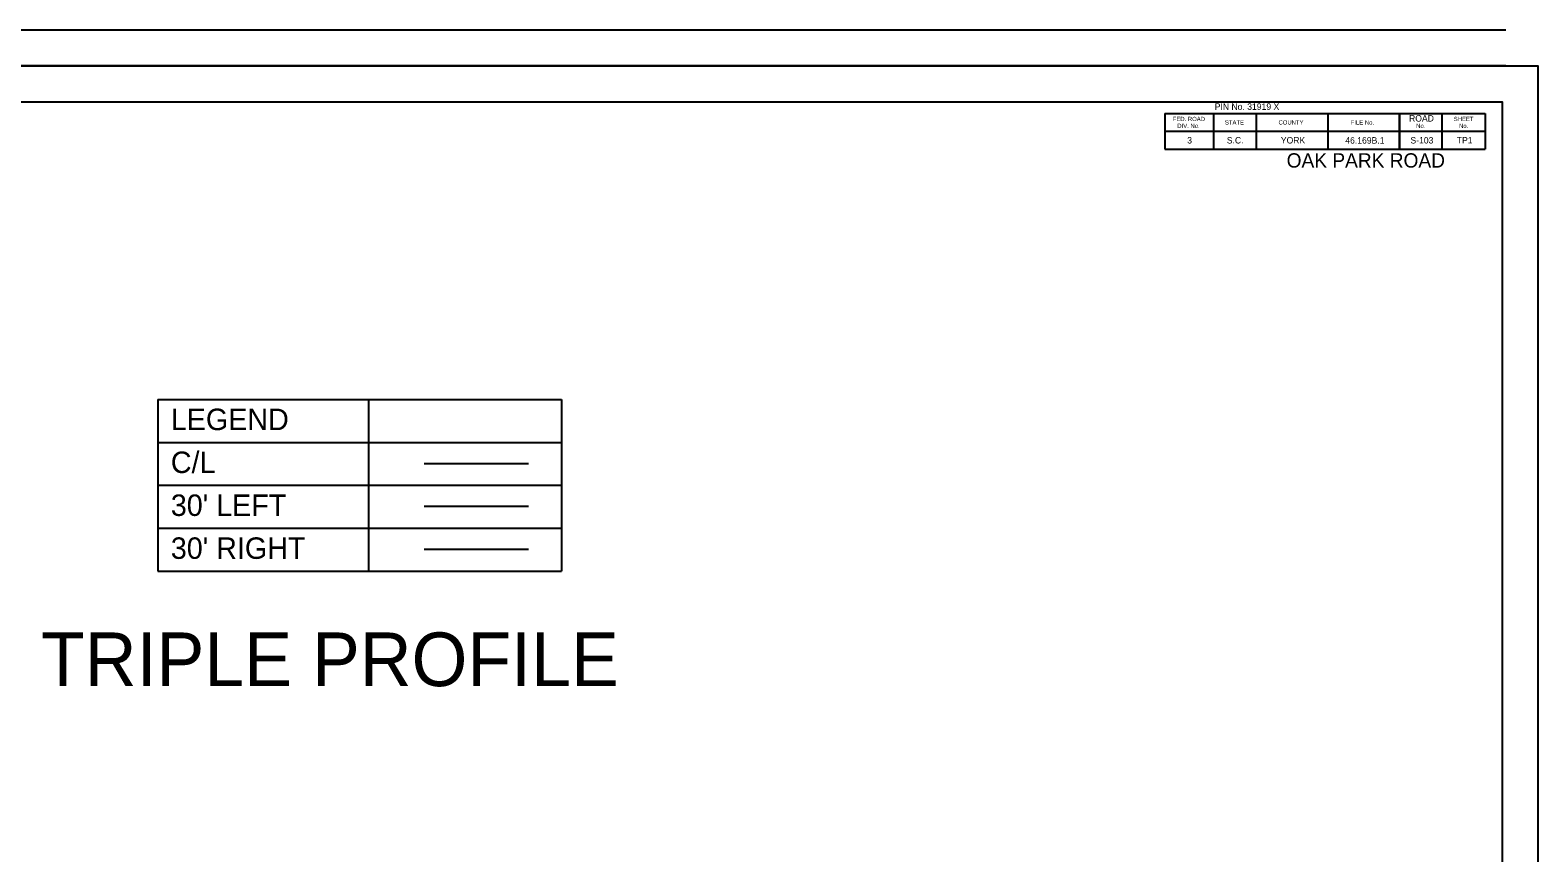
# Model space of a CAD drawing. Extents: x 178884 to 181858, y 178732 to 179192.
# Drawn here: x 179181.1 to 179602.8, y 178962.4 to 179192.4 of the extents above; entities that cross this region are included whole.
import ezdxf

# ---------------------------------------------------------------- set-up
doc = ezdxf.new("R2010")
doc.units = 0
for name, color, linetype in [('RD_SHT_Bndy', 7, 'Continuous'), ('RD_SHT_IplotShp', 7, 'Continuous'), ('RD_SHT_TX', 7, 'Continuous'), ('RD_TX_Misc2', 7, 'Continuous')]:
    doc.layers.add(name, color=color, linetype=linetype)

msp = doc.modelspace()

# ---------------------------------------------------------------- linework, layer by layer
at = {"layer": 'RD_SHT_Bndy'}
for p, q in [((179593.83, 179192.39), (178889.83, 179192.39)), ((179593.83, 179182.39), (178889.83, 179182.39)), ((179498.43, 179169.11), (179498.43, 179159.11)), ((179498.43, 179169.11), (179564.03, 179169.11)), ((179512.03, 179169.11), (179512.03, 179159.11)), ((179524.03, 179159.11), (179524.03, 179169.11)), ((179544.03, 179169.11), (179544.03, 179159.11)), ((179564.03, 179159.11), (179564.03, 179169.11)), ((179564.03, 179169.11), (179564.03, 179159.11)), ((179564.03, 179169.11), (179588.03, 179169.11)), ((179576.03, 179159.11), (179576.03, 179169.11)), ((179588.03, 179169.11), (179588.03, 179159.11)), ((179498.43, 179164.11), (179564.03, 179164.11)), ((179564.03, 179164.11), (179588.03, 179164.11)), ((179498.43, 179159.11), (179564.03, 179159.11)), ((179564.03, 179159.11), (179588.03, 179159.11))]:
    msp.add_line(p, q, dxfattribs=at)
msp.add_lwpolyline([(178922.77, 179172.39), (179592.77, 179172.39), (179592.77, 178752.39), (178922.77, 178752.39)], close=True, dxfattribs=at)
at = {"layer": 'RD_SHT_IplotShp'}
msp.add_lwpolyline([(178884.41, 179182.39), (179602.77, 179182.39), (179602.77, 178742.39), (178884.41, 178742.39)], close=True, dxfattribs=at)
at = {"layer": 'RD_TX_Misc2'}
for p, q in [((179216.78, 179089.16), (179329.68, 179089.16)), ((179216.78, 179089.16), (179216.78, 179041.16)), ((179275.68, 179089.16), (179275.68, 179041.16)), ((179329.68, 179089.16), (179329.68, 179041.16)), ((179216.78, 179077.16), (179329.68, 179077.16)), ((179291.25, 179071.28), (179320.44, 179071.28)), ((179216.78, 179065.16), (179329.68, 179065.16)), ((179291.25, 179059.28), (179320.44, 179059.28)), ((179216.78, 179053.16), (179329.68, 179053.16)), ((179291.25, 179047.28), (179320.44, 179047.28)), ((179216.78, 179041.16), (179329.68, 179041.16))]:
    msp.add_line(p, q, dxfattribs=at)

# ---------------------------------------------------------------- texts
at = {"layer": 'RD_SHT_TX'}
for s, height, p in [('PIN No. 31919 X          ', 1.8, (179512.38, 179170.12)), ('FED. ROAD', 1.2, (179500.65, 179166.97)), ('STATE', 1.2, (179515.24, 179166.01)), ('COUNTY', 1.2, (179530.23, 179166.01)), ('FILE No.', 1.2, (179550.43, 179166.01)), ('      ROAD      ', 1.8, (179562.73, 179166.84)), ('SHEET', 1.2, (179579.26, 179166.97)), ('DIV. No.', 1.2, (179501.92, 179165.05)), ('No.', 1.2, (179568.73, 179165.05)), ('No.', 1.2, (179580.73, 179165.05)), ('3', 1.8, (179504.69, 179160.71)), ('S.C.', 1.8, (179515.77, 179160.71)), ('      YORK      ', 1.8, (179526.87, 179160.71)), ('   46.169B.1    ', 1.8, (179546.9, 179160.68)), ('     S-103      ', 1.8, (179563.79, 179160.71)), ('      TP1       ', 1.8, (179576.08, 179160.71)), ('         OAK PARK ROAD        ', 4, (179519.13, 179153.98))]:
    msp.add_text(s, height=height, dxfattribs=at).set_placement(p)
at = {"layer": 'RD_TX_Misc2'}
for s, height, p in [('LEGEND', 6, (179220.4, 179080.58)), ('C/L ', 6, (179220.4, 179068.58)), ("30' LEFT", 6, (179220.4, 179056.58)), ("30' RIGHT", 6, (179220.4, 179044.58)), ('TRIPLE PROFILE', 15, (179184.08, 179009))]:
    msp.add_text(s, height=height, dxfattribs=at).set_placement(p)

doc.saveas('drawing.dxf')
